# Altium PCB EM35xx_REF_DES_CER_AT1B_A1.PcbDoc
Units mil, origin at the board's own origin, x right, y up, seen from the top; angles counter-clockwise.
Board outline 1630 x 1016 mil, 2 copper layers (Top Layer, Bottom Layer), stack 60.8 mil thick; 50 components, 47 nets, 208 pads, 114 vias.
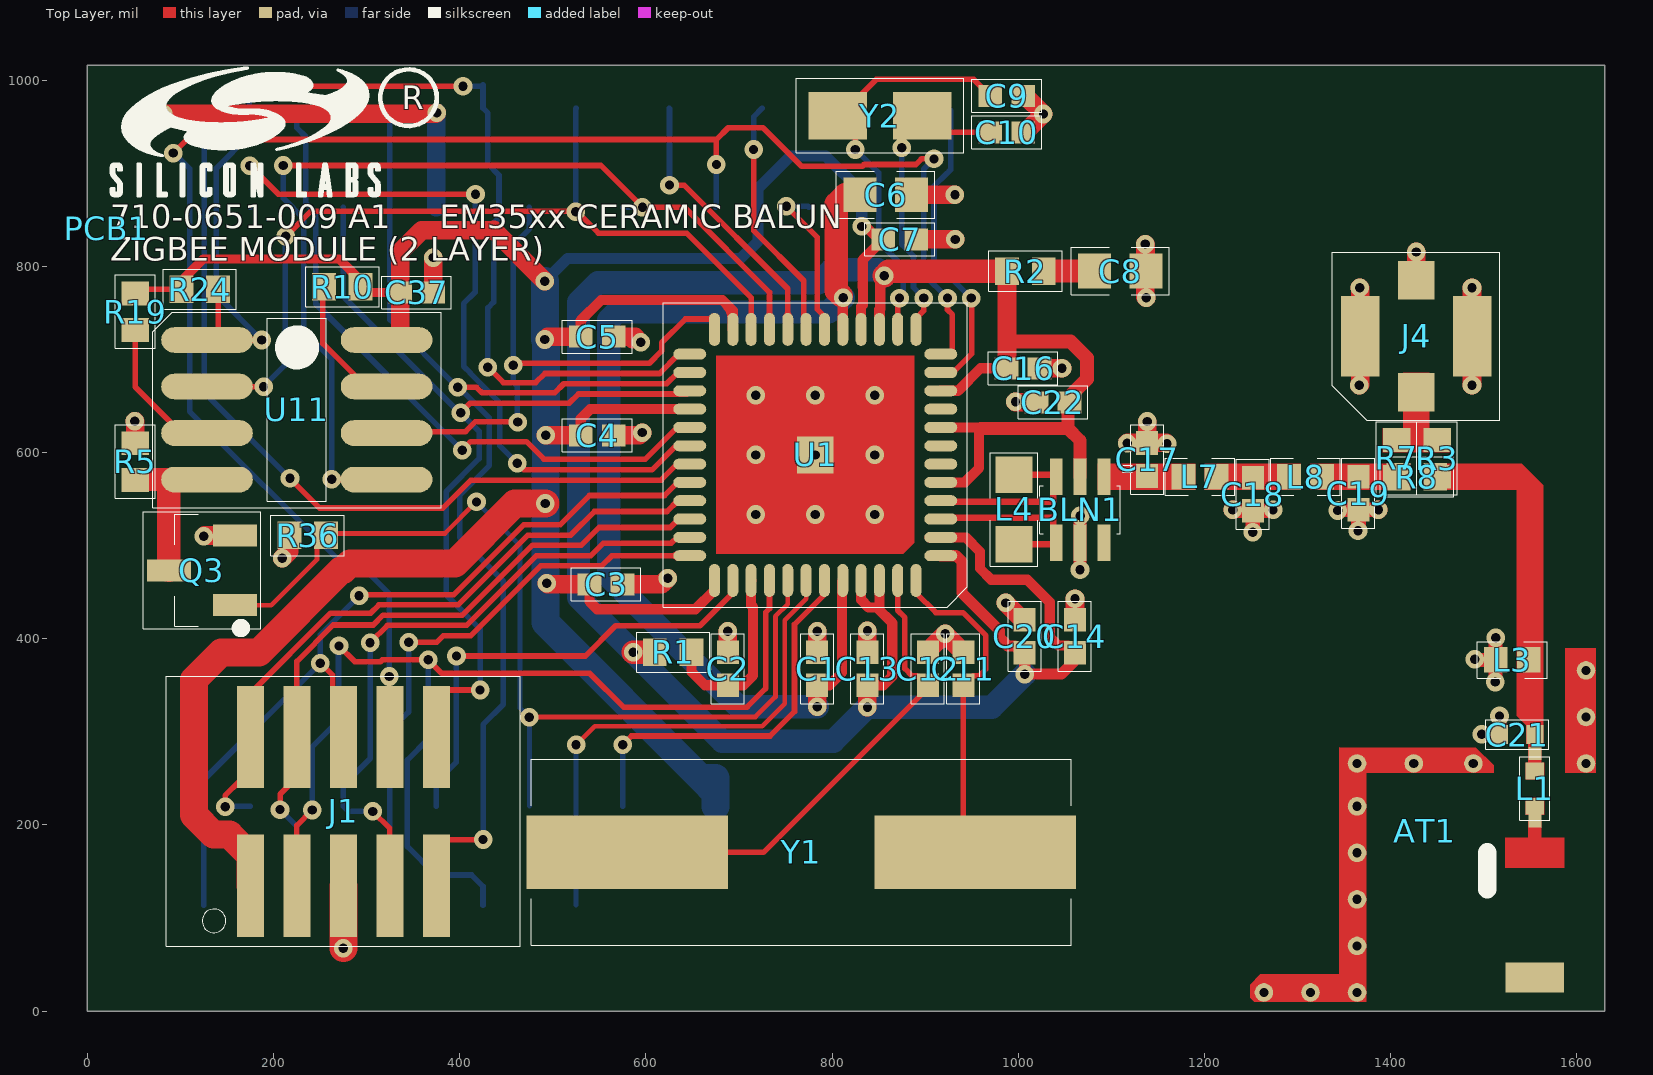
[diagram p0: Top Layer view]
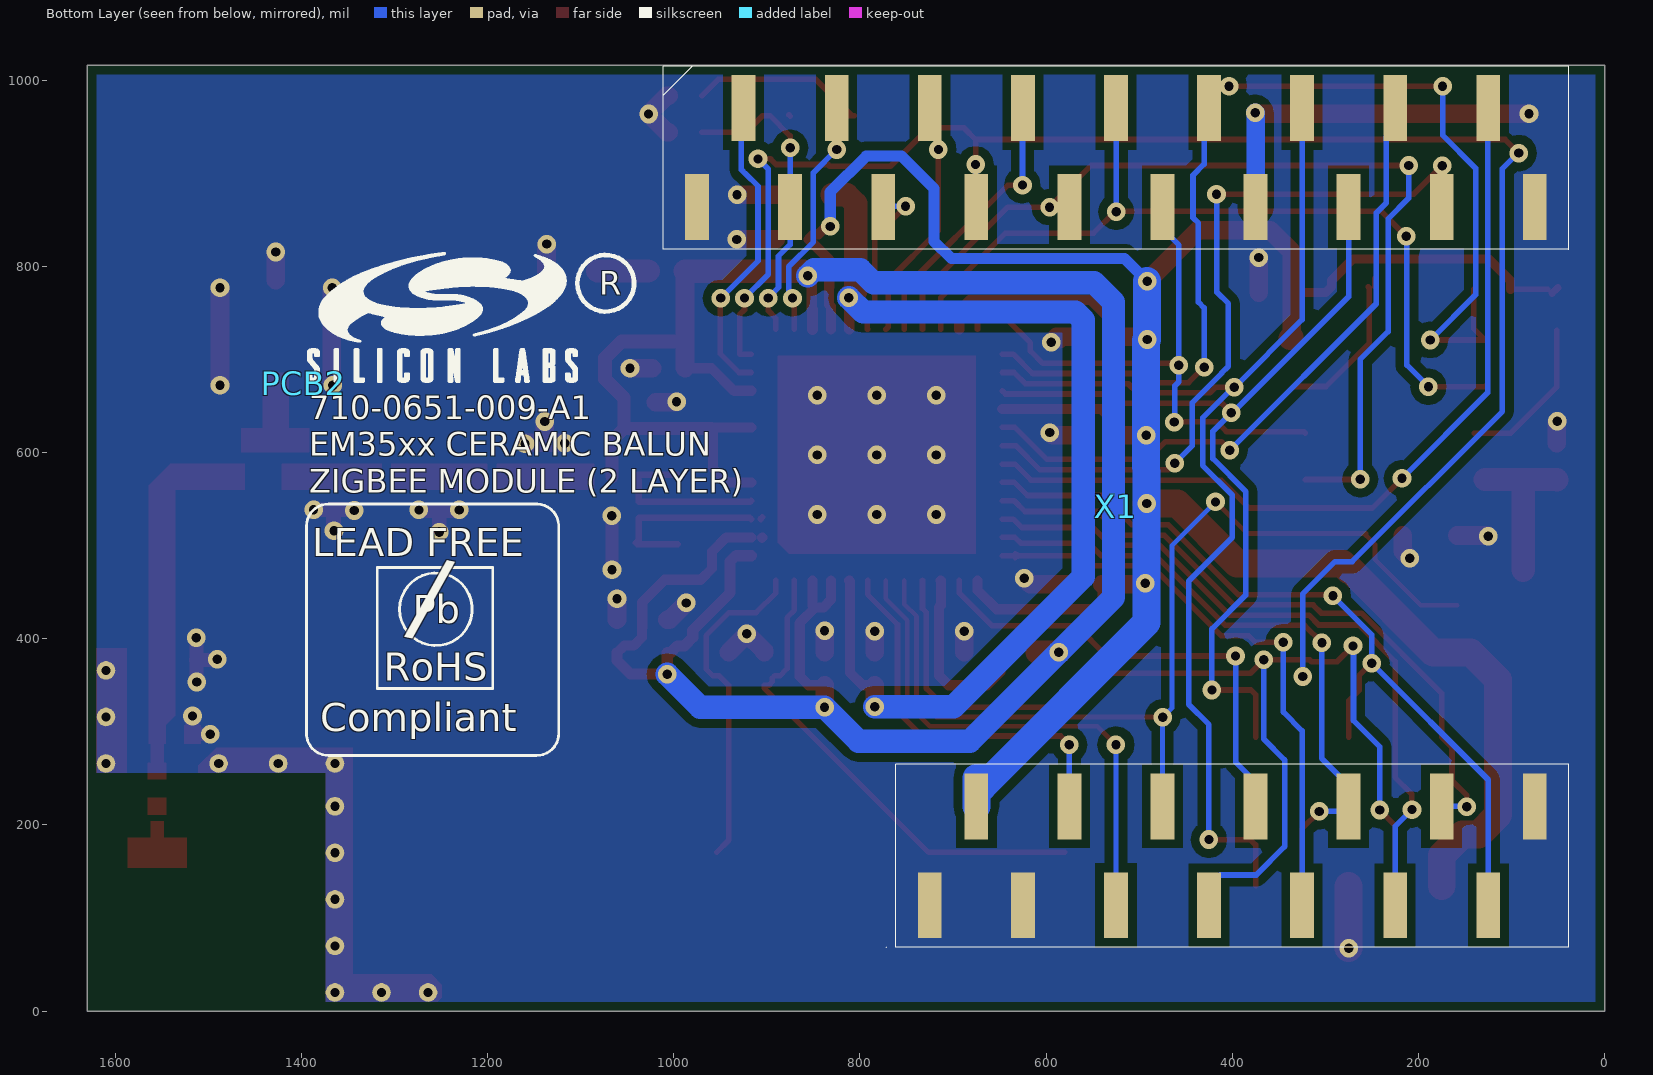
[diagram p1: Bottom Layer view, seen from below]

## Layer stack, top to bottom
Top Solder: solder mask 0.4, Solder Resist, Dk 3.5
Top Layer: signal copper 1.4
Dielectric1: prepreg 58, HR370, Dk 3.9
Bottom Layer: signal copper 1.4
Bottom Solder: solder mask 0.4, Solder Resist, Dk 3.5

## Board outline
0,0 1630,0 1630,1016 0,1016

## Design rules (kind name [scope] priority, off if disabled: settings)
AssemblyTestpoint [All] p1: testpointundercomponent=TRUE minsize=30 maxsize=40 preferedsize=40 minholesize=0 maxholesize=10 preferedholesize=10 testpointgrid=1 usegrid=TRUE gridtolerance=0.01 allowsidetop=TRUE allowsidebottom=TRUE
Clearance "Schematic Clearance Constraint_2" [InNetClass('R8_Nets')] p1: gap=6
Clearance "Schematic Clearance Constraint_1" [InNetClass('R3_Nets')] p2: gap=6
Clearance "Schematic Clearance Constraint" [InNetClass('R7_Nets')] p3: gap=6
Clearance "Schematic Clearance Constraint_6" [InNet('GND')] p4: gap=9.5
Clearance "Schematic Clearance Constraint_5" [InNetClass('L1_Nets')] p5: gap=6
Clearance "Schematic Clearance Constraint_4" [InNetClass('L7_Nets')] p6: gap=6
Clearance "Schematic Clearance Constraint_3" [InNetClass('L8_Nets')] p7: gap=6
Clearance PCB_Only [(InComponentClass('PCB Only'))] p8: gap=0
Clearance [All] p9: gap=5
ComponentClearance ComponentClearance_L1_AT1 [InComponent('AT1') vs InComponent('L1')] p1: gap=0 collisioncheckmode=3 verticalgap=0 showdistances=TRUE
ComponentClearance ComponentClearance_L1_L5 [InComponent('L5') vs InComponent('L1')] p2: gap=0 collisioncheckmode=3 verticalgap=0 showdistances=TRUE
ComponentClearance ComponentClearance_L5_AT1 [InComponent('AT1') vs InComponent('L5')] p3: gap=0 collisioncheckmode=3 verticalgap=0 showdistances=TRUE
ComponentClearance ComponentClearance_1 [All] p4: gap=10 collisioncheckmode=3 verticalgap=10 showdistances=FALSE
DiffPairsRouting [All] p1: maxlimit=10 minlimit=10 mostfreqgap=10 toplayer_minwidth=15 toplayer_maxwidth=15 toplayer_prefwidth=15 bottomlayer_minwidth=15 bottomlayer_maxwidth=15 bottomlayer_prefwidth=15 maxuncoupledlength=500
FabricationTestpoint [All] p1: side=3 testpointundercomponent=TRUE minsize=30 maxsize=40 preferedsize=40 minholesize=0 maxholesize=10 preferedholesize=10 testpointgrid=1 allowsidetop=TRUE allowsidebottom=TRUE usegrid=TRUE gridtolerance=0.01
HoleSize [All] p1: absolutevalues=TRUE maxlimit=100 minlimit=10 maxpercent=80.000 minpercent=20.000
MatchedLengths "Schematic Matched Net Lengths" [InNetClass('L4_Nets')] p1: tolerance=2.5 checknetsindiffpair=TRUE checkdiffpairvsdiffpair=FALSE checkothers=FALSE
MinimumSolderMaskSliver [All] p1: minsoldermaskwidth=2
PlaneClearance [All] p1: clearance=10
PlaneConnect [All] p1: planeconnectstyle=Direct reliefexpansion=20 reliefentries=4 reliefconductorwidth=10 reliefairgap=10
PolygonConnect PolygonConnect_3 [All vs IsNamedPolygon('GROUND')] p1: connectstyle=Direct reliefconductorwidth=10 reliefentries=4 polygonreliefangle="90 Angle" airgapwidth=10
PolygonConnect PolygonConnect_2 [All vs IsNamedPolygon('GROUND')] p2: connectstyle=Direct reliefconductorwidth=10 reliefentries=4 polygonreliefangle="90 Angle" airgapwidth=10
PolygonConnect PolygonConnect_1 [All vs IsNamedPolygon('GROUND')] p3: connectstyle=Relief reliefconductorwidth=10 reliefentries=4 polygonreliefangle="90 Angle" airgapwidth=10
PolygonConnect [All] p4: connectstyle=Direct reliefconductorwidth=10 reliefentries=4 polygonreliefangle="90 Angle" airgapwidth=10
RoutingVias [All] p1: holewidth=10 width=20 viastyle="Through Hole" minholewidth=10 minwidth=20 maxholewidth=10 maxwidth=40
ShortCircuit "Schematic Short-Circuit Constraint" [InNet('GND')] p1: allowed=TRUE
ShortCircuit ShortCircuit_AT1_GND [InNet('NetAT1_1') vs InNet('GND')] p2: allowed=TRUE
ShortCircuit ShortCircuit_AT1_L1 [InPolygon vs InNet('NetL1_1')] p3: allowed=TRUE
ShortCircuit [All] p4: allowed=FALSE
SilkToSilkClearance SilkToSilkClearance_1 [(InComponentClass('PCB Only')) vs (InComponentClass('PCB Only'))] p1: silktosilkclearance=0
SilkToSilkClearance SilkToSilkClearance_2 [InComponent('U11')] p2: silktosilkclearance=0
SilkToSilkClearance SilkToSilkClearance_L1 [InComponent('L1')] p3: silktosilkclearance=0
SilkToSilkClearance SilkToSilkClearance_L5 [InComponent('L5')] p4: silktosilkclearance=0
SilkToSilkClearance [All] p5: silktosilkclearance=0.1
SilkToSolderMaskClearance SilkscreenOverComponent_L1 [InComponent('AT1') vs InComponent('L1')] p1: minsilkscreentomaskgap=0 clearancetoexposedcopper=TRUE
SilkToSolderMaskClearance SilkscreenOverComponent_AT1 [InComponent('AT1')] p2: minsilkscreentomaskgap=0 clearancetoexposedcopper=TRUE
SilkToSolderMaskClearance SilkscreenOverComponent_L5_1 [InComponent('AT1') vs InComponent('L5')] p3: minsilkscreentomaskgap=0 clearancetoexposedcopper=TRUE
SilkToSolderMaskClearance SilkscreenOverComponentPads [IsPad] p4: minsilkscreentomaskgap=0.1 clearancetoexposedcopper=TRUE
SolderMaskExpansion [All] p1: expansion=1
Width "Schematic Width Constraint_3" [InNetClass('R3_Nets')] p1: maxlimit=60 minlimit=6 preferedwidth=28
Width "Schematic Width Constraint_2" [InNetClass('R8_Nets')] p2: maxlimit=60 minlimit=6 preferedwidth=28
Width "Schematic Width Constraint_1" [InNetClass('R7_Nets')] p3: maxlimit=60 minlimit=6 preferedwidth=28
Width "Schematic Width Constraint_14" [InNetClass('C22_Nets')] p4: maxlimit=40 minlimit=5 preferedwidth=20
Width "Schematic Width Constraint_13" [InNetClass('C6_Nets')] p5: maxlimit=40 minlimit=5 preferedwidth=20
Width "Schematic Width Constraint_12" [InNetClass('C37_Nets')] p6: maxlimit=40 minlimit=5 preferedwidth=20
Width "Schematic Width Constraint_11" [InNetClass('L1_Nets')] p7: maxlimit=60 minlimit=6 preferedwidth=28
Width "Schematic Width Constraint_10" [InNetClass('L7_Nets')] p8: maxlimit=60 minlimit=6 preferedwidth=28
Width "Schematic Width Constraint_9" [InNetClass('L8_Nets')] p9: maxlimit=60 minlimit=6 preferedwidth=28
Width "Schematic Width Constraint" [InNetClass('L4_Nets')] p10: maxlimit=10 minlimit=5 preferedwidth=7
Width [All] p11: maxlimit=40 minlimit=4 preferedwidth=5
18 further rules are at their usual default settings.

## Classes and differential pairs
component class "PCB Only": AT1 PCB1 PCB2
net class AT1_Nets: GND NetAT1_1 NetAT1_4
net class BLN1_Nets: 1V8 GND NetBLN1_1 NetBLN1_6 RF_N RF_P
net class C1_Nets: 1V2_CORE GND
net class C2_Nets: GND NetC2_1
net class C3_Nets: GND VBRD
net class C4_Nets: GND VBRD
net class C5_Nets: GND VBRD
net class C6_Nets: 1V2_CORE GND
net class C7_Nets: GND VBRD
net class C8_Nets: GND NetC8_1
net class C9_Nets: GND PC7
net class C10_Nets: GND PC6
net class C11_Nets: GND OSCA
net class C12_Nets: GND OSCB
net class C13_Nets: 1V8 GND
net class C14_Nets: 1V8 GND
net class C16_Nets: 1V8 GND
net class C17_Nets: GND NetBLN1_1
net class C18_Nets: GND NetC18_1
net class C19_Nets: GND NetC19_1
net class C20_Nets: 1V8 GND
net class C22_Nets: 1V8 GND
net class C37_Nets: GND VBRD
net class J1_Nets: GND JCLK NRESET PA4 PA5 PC0 PC2 PC3 PC4 VBRD
net class J4_Nets: GND NetJ4_1
net class L1_Nets: NetAT1_1 NetAT1_4
net class L3_Nets: GND NetAT1_4
net class L4_Nets: RF_N RF_P
net class C21_Nets: GND NetAT1_4
net class L7_Nets: NetBLN1_1 NetC18_1
net class L8_Nets: NetC18_1 NetC19_1
net class Q3_Nets: GND NSF_GND PB7
net class R1_Nets: 1V8 NetC2_1
net class R2_Nets: 1V8 NetC8_1
net class R3_Nets: NetAT1_4 NetJ4_1
net class R5_Nets: GND NSF_GND
net class R7_Nets: NetC19_1 NetJ4_1
net class R8_Nets: NetAT1_4 NetC19_1
net class R10_Nets: NSF_HOLD VBRD
net class R19_Nets: NSF_WP VBRD
net class R24_Nets: PA3 VBRD
net class R36_Nets: GND PB7
net class U1_Nets: 1V2_CORE 1V8 GND JCLK NetC2_1 NetU1_9 NRESET OSCA OSCB PA0 PA1 PA2 PA3 PA4 PA5 PA6 PA7 PB0 PB1 PB2 PB3 PB4 PB5 PB6 PB7 PC0 PC1 PC2 PC3 PC4 PC5 PC6 PC7 RF_N RF_P TX_ALT_N TX_ALT_P VBRD
net class U11_Nets: NSF_GND NSF_HOLD NSF_WP PA0 PA1 PA2 PA3 VBRD
net class X1_Nets: GND JCLK NRESET PA0 PA1 PA2 PA3 PA4 PA5 PA6 PA7 PB0 PB1 PB2 PB3 PB4 PB5 PB6 PB7 PC0 PC1 PC2 PC3 PC4 PC5 PC6 PC7 VBRD
net class Y1_Nets: OSCA OSCB
net class Y2_Nets: PC6 PC7
differential pair RF: +RF_P -RF_N

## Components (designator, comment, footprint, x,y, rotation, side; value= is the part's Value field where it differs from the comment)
AT1 "Value" Ant-Johanson-2450AT18B100 1630,0 r0 top
BLN1 "CHIP MULTILAYER CERAMIC, 2.4 GHZ. 50/100 Ohm" BLN_0805 1092,574 r0 top
C1 "10NF" C_0402 784,350 r0 top
C2 "0.47uF" C_0402 688,350 r0 top
C3 "0.1uF" C_0402 539.56,458.5 r270 top
C4 "0.1uF" C_0402 530,618.5 r270 top
C5 "0.1uF" C_0402 530,724.5 r270 top
C6 "1.0uF" C_0603 830,877 r0 top
C7 "0.1uF" C_0402 855,829 r270 top
C8 "2.2uF" C_0603 1082,795 r0 top
C9 "33pF, (DNI)" C_0402 970,983.2 r270 top
C10 "22PF, (DNI)" C_0402 970,944.1 r270 top
C11 "22PF" C_0402 941,350 r0 top
C12 "22PF" C_0402 903,350 r0 top
C13 "10pF" C_0402 838,350 r0 top
C14 "10NF" C_0402 1061,385 r0 top
C16 "10NF" C_0402 987.56,690.5 r270 top
C17 "1pF" C_0402 1138.5,575 r0 top
C18 "1.8pF" C_0402 1252,573 r180 top
C19 "1pF" C_0402 1365.5,574 r180 top
C20 "10NF" C_0402 1007,385 r0 top
C21 "0.75pF" C_0402_Johanson_AT1B 1555.1,297.1 r90 top
C22 "10pF" C_0402 1055,654 r90 top
C37 "10NF, (DNI)" C_0402 336.06,772 r270 top
J1 "FTSH-105-01-F-DV-K, (DNI)" 610-0019-000-REF-DES 175,134.5 r270 top
J4 "U.FL, (DNI)" UFL-R-SMT_1 1427.5,725 r180 top
L1 "5n6H" C_0402_Johanson_AT1B 1555,258 r180 top
L3 "DNI" L_0402 1548.5,377.3 r180 top
L4 "2.7nH" L_0603 995.5,576.3 r0 top
L7 "2n7H" L_0402 1177.56,574 r0 top
L8 "2n7H" L_0402 1291,574 r0 top
LOGO1 "SiliconLabsLogo_100" SiliconLabsLogo_100_Mech-16 3297,-1825.5 r0 top
PCB1 "EM35x Ceramic Balun 2 Layer Reference Design Corporate Logo" 710-0651-009 20.7,840.9 r0 top
PCB2 "Bottom Silk Screen ID and RoHS Text" 710-0651-009_ROHS 1397.6,674.7 r180 bottom
Q3 "2N7002, (DNI)" SOT23-3L 123,473.5 r180 top
R1 "10 Ohm" R_0402 609.63,385.5 r0 top
R2 "1 Ohm" R_0402 988,795 r0 top
R3 "0_OHM, (DNI)" R_0402 1450,574 r90 top
R5 "0_OHM, (DNI)" R_0402 51.4,570.7 r90 top
R7 "0_OHM, (DNI)" R_0402 1406.5,574 r90 top
R8 "0_OHM" R_0402 1408.63,574 r0 top
R10 "100K, (DNI)" R_0402 254.06,778.11 r0 top
R19 "100K, (DNI)" R_0402 51.4,731.63 r90 top
R24 "100K, (DNI)" R_0402 140.5,775.5 r180 top
R36 "100K, (DNI)" R_0402 256.37,511 r180 top
U1 "EM35xx" EM357 782,597.5 r0 top
U11 "2M, (DNI)" SOIC127P600-8M 225,646 r0 top
X1 "Dual Row Socket, (DNI)" EM35X_RCM_MODULE_SIDE_SMT 975,916.85 r180 bottom locked
Y1 "24.000MHZ, 18PF LOAD" HC-49-SMD 767,170.5 r180 top
Y2 "32.768KHz, 12.5pF, (DNI)" IL3X 851.5,962 r180 top

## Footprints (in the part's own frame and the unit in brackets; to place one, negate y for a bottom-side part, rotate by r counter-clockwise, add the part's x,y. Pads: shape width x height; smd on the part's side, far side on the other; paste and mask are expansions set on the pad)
610-0019-000-REF-DES [mil] "old footprint with keepout for cable connector"
  rect 110x29 smd: 1(0,0) 2(-160,0) 3(0,50) 4(-160,50) 5(0,100) 6(-160,100) 7(0,150) 8(-160,150) 9(0,200) 10(-160,200)
  silkscreen extent -225,-90 65,290, body extent -148,-25 -12,225, height 225
710-0651-009 [mil] "EM35x Ceramic Balun"
  silkscreen extent 5,35 355,173
710-0651-009_ROHS [mil] "EM35x CERAMIC BALUN"
  silkscreen extent 3,-400 355,139
Ant-Johanson-2450AT18B100 [mil]
  rect 14x14 smd paste-100 mask-100: 1(-75,204) 3(-113.17,296.9) 4(-74.99,276.7)
  rect 63x32 smd paste+0 mask+0: 2(-75,36)
  round 20 hole 10 mask+0: 5(-20,366) 6(-20,316) 7(-20,266) 8(-141,266) 9(-205,266) 10(-266,266) 11(-266,220) 12(-266,170) 13(-266,120) 14(-266,70) 15(-266,20) 17(-316,20) 18(-366,20)
  Top Layer region: -68,186 -68,204 -82,204 -82,186
  Top Layer region: -43.5,154 -43.5,186 -106.5,186 -106.5,154
  Top Layer region: -65,267 -85,267 -85,249 -65,249
  Top Layer region: -65,229 -85,229 -85,211 -65,211
  Top Layer region: -122,307 -122,287 -104,287 -104,307
  Top Layer region: -84,307 -84,287 -66,287 -66,307
  Top Layer region: -68,267 -68,287 -82,287 -82,267
  Multi-Layer pour cut-out: -256,0 -256,256 0,256 0,0
  silkscreen extent -126,131 -126,170, body extent -114,40 -43,307, height 40
BLN_0805 [mm]
  rect 0.35x1 smd: 1(0,0) 2(-0.65,0) 3(-1.3,0) 4(-1.3,-1.8) 5(-0.65,-1.8) 6(0,-1.8)
  silkscreen extent -1.75,-1.55 0.78,0.31
C_0402 [mm]
  rect 0.6x0.65 smd mask+0.051: 1(0,0) 2(0,0.9)
  silkscreen extent -0.45,-0.5 0.45,1.4, body extent -0.28,-0.05 0.28,0.97, height 1.02
C_0402_Johanson_AT1B [mil] "Special footprint for Antenna"
  rect 20x18 smd paste+0 mask+0: 1(0,0) 2(0,38)
  silkscreen extent -16,-15 16,53
C_0603 [mm]
  rect 0.9x0.95 smd mask+0.051: 1(0,0) 2(1.4,0)
  silkscreen extent -0.64,-0.65 2.04,0.65, body extent -0.09,-0.39 1.51,0.39, height 0.89
EM35X_RCM_MODULE_SIDE_SMT [mm]
  rect 0.65x1.8 smd: 1(0,-1.35) 2(1.27,1.35) 3(2.54,-1.35) 4(3.81,1.35) 5(5.08,-1.35) 6(6.35,1.35) 7(7.62,-1.35) 8(8.89,1.35) 9(10.16,-1.35) 10(11.43,1.35) 11(12.7,-1.35) 12(13.97,1.35) 13(15.24,-1.35) 14(16.51,1.35) 15(17.78,-1.35) 16(19.05,1.35) 17(20.32,-1.35) 18(21.59,1.35) 19(22.86,-1.35) 20(22.86,-17.7) 21(21.59,-20.4) 22(20.32,-17.7) 23(19.05,-20.4) 24(17.78,-17.7) 25(16.51,-20.4) 26(15.24,-17.7) 27(13.97,-20.4) 28(12.7,-17.7) 29(11.43,-20.4) 30(10.16,-17.7) 31(8.89,-20.4) 32(7.62,-17.7) 33(6.35,-20.4)
  silkscreen extent -0.93,-21.56 23.78,2.5
EM357 [mm]
  oval 0.9x0.3 smd paste+0 mask+0: 1(3.425,-2.75) 2(3.425,-2.25) 3(3.425,-1.75) 4(3.425,-1.25) 5(3.425,-0.75) 6(3.425,-0.25) 7(3.425,0.25) 8(3.425,0.75) 9(3.425,1.25) 10(3.425,1.75) 11(3.425,2.25) 12(3.425,2.75) 25(-3.425,2.75) 26(-3.425,2.25) 27(-3.425,1.75) 28(-3.425,1.25) 29(-3.425,0.75) 30(-3.425,0.25) 31(-3.425,-0.25) 32(-3.425,-0.75) 33(-3.425,-1.25) 34(-3.425,-1.75) 35(-3.425,-2.25) 36(-3.425,-2.75)
  oval 0.3x0.9 smd paste+0 mask+0: 13(2.75,3.425) 14(2.25,3.425) 15(1.75,3.425) 16(1.25,3.425) 17(0.75,3.425) 18(0.25,3.425) 19(-0.25,3.425) 20(-0.75,3.425) 21(-1.25,3.425) 22(-1.75,3.425) 23(-2.25,3.425) 24(-2.75,3.425) 37(-2.75,-3.425) 38(-2.25,-3.425) 39(-1.75,-3.425) 40(-1.25,-3.425) 41(-0.75,-3.425) 42(-0.25,-3.425) 43(0.25,-3.425) 44(0.75,-3.425) 45(1.25,-3.425) 46(1.75,-3.425) 47(2.25,-3.425) 48(2.75,-3.425)
  rect 1x1 smd paste-1 mask+0: 49(0,0)
  Top Layer pour cut-out: -3.039,-3.503 -3.499,-3.503 -3.499,-3.043 -3.039,-3.043 -3.039,-3.503
  Top Layer pour cut-out: -3.039,3.04 -3.499,3.04 -3.499,3.5 -3.039,3.5 -3.039,3.04
  Top Layer pour cut-out: 3.507,3.04 3.047,3.04 3.047,3.5 3.507,3.5 3.507,3.04
  Top Layer pour cut-out: 3.506,-3.505 3.046,-3.505 3.046,-3.045 3.506,-3.045 3.506,-3.505
  Top Layer region: 2.7,-2.4 2.4,-2.7 -2.7,-2.7 -2.7,2.7 2.7,2.7
  silkscreen extent -4.15,-4.15 4.15,4.15, body extent -3.51,-3.51 3.51,3.51, height 0.9
HC-49-SMD [mm]
  rect 5.5x2 smd: 1(-4.75,0) 2(4.75,0)
  silkscreen extent -7.37,-2.54 7.37,2.54, body extent -7.24,-2.41 7.24,2.41, height 4.06
IL3X [mil]
  rect 62.99x51.18 smd: 1(-45.28,0) 2(45.28,0)
  silkscreen extent -90,-40 90,40, body extent -63,-30 63,30, height 36
L_0402 [mm]
  rect 0.65x0.7 smd: 1(0,0) 2(0.9,0)
  silkscreen extent -0.5,-0.5 1.4,0.5, body extent -0.06,-0.28 0.95,0.28, height 1.02
L_0603 [mm]
  rect 1x1 smd: 1(0,0) 2(0,-1.9)
  silkscreen extent -0.65,-2.5 0.65,0.6, body extent -0.39,-1.74 0.39,-0.14, height 0.89
R_0402 [mm]
  rect 0.65x0.75 smd: 1(0,0) 2(1,0)
  silkscreen extent -0.5,-0.55 1.5,0.55, body extent -0.01,-0.28 1,0.28, height 1.02
SiliconLabsLogo_100_Mech-16 [mil] "Silicon Labs Logo for Sheet Layer"
SOIC127P600-8M [mm] "SOIC, 8-Leads, Body 4.9x3.9mm, Pitch 1.27mm, IPC Low Density"
  oval 2.5x0.7 smd: 1(-2.45,1.905) 2(-2.45,0.635) 3(-2.45,-0.635) 4(-2.45,-1.905) 5(2.45,-1.905) 6(2.45,-0.635) 7(2.45,0.635) 8(2.45,1.905)
  silkscreen extent -3.94,-2.67 3.94,2.67, body extent -2,-2.5 2,2.5, height 1.75
SOT23-3L [mm] "SOT23, 3-Leads, Body 2.9x1.3mm, Pitch 0.95mm, Lead Span 2.5mm, IPC High Density"
  rect 1.2x0.6 smd: 1(-0.9,0.95) 2(-0.9,-0.95) 3(0.9,0)
  silkscreen extent -1.6,-1.6 1.6,1.7, body extent -0.7,-1.5 0.7,1.5, height 1.1
UFL-R-SMT_1 [mm]
  rect 1x1.05 smd: 1(0,1.525) 4(0,-1.525)
  rect 1.05x2.2 smd: 2(-1.525,0) 3(1.525,0)
  silkscreen extent -2.29,-2.29 2.29,2.29

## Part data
AT1: library part 600-0044-000
BLN1: library part 566-0075-000, "Balun 0805"
C1 C14 C16 C20: library part 550-0036-000
C2: library part 550-0037-000
C3 C4 C5 C7: library part 550-0034-000
C6: library part 550-0033-000
C8: library part 550-0038-000
C9: library part 550-0039-000-DNI
C10: library part 550-2201-050-DNI
C11 C12: library part 550-2201-050
C13 C21 C22: library part 550-1001-050
C17 C19: library part 550-0040-000
C18: library part 550-1P8A-050
C37: library part 550-1032-025-DNI
J1: library part 610-0045-000-DNI, "CONNECTOR, HEADER, SHROUDED, 10 POSITION, DUAL ROW, VERTICAL, 0.050\""
J4: library part 610-0081-000-DNI, "U.FL RF Coaxial Connector"
L1: library part 566-0077-000, "Design Placeholder"
L3: library part 566-0000-TBD, "Design Placeholder"
L4: library part 566-0076-000, "Design Placeholder"
L7 L8: library part 566-2N7A-000, "Design Placeholder"
LOGO1: "Company Logo in PCB Title Block"
PCB1: library part 710-0651-009, "PCB BoM ID and Top Side Silk Screen Identifier"
PCB2: library part 710-0651-009_ROHS, "Bottom Side Silk Screen Identifier"
Q3: library part 545-0047-000-DNI, "MOSFET N-Channel"
R1: library part 555-1001-010
R2: library part 555-1R05-016
R3 R5 R7: library part 555-0000-000-DNI
R8: library part 555-0000-000
R10 R19 R24 R36: library part 555-1045-016-DNI
U1: library part 540-035XX-000, "IC, EM357, ZIGBEE/802.15.4 RF SOLUTION, ARM CORTEX-M3, 12K RAM, 192K FLASH, QFN-48"
U11: library part 510-1040-000-DNI, "IC - MEMORY, SERIAL FLASH, 2M (2M X 1, 1M X 2), 2.7 V - 3.6 V, -40C  85C, 8-SOIC (0.154\", 3.90MM WIDTH)"
X1: library part 610-0010-DNI, "610-0010-DNI"
Y1: library part 565-2400-009, "OSCILLATOR, CRYSTAL, 24.000MHZ, 18PF LOAD, +/-10PPM TOLERANCE, +/-25PPM STABILITY, -40C TO 85C, AT49"
Y2: library part 565-3271-001-DNI

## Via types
v1: diameter 20, hole 10, Top Layer to Bottom Layer, 114 vias

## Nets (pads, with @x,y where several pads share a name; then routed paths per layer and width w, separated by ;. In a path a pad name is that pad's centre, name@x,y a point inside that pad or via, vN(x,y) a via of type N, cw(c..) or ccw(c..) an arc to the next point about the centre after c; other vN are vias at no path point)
1V2_CORE: C1.1 C6.1 U1.17 U1.44 | length 1141.5
  Top Layer w11: C1.1 797,350 810.81,363.81 810.81,461.94 U1.44 ; U1.17 811.53,766.03 v1(812,766.5) v1@812,768.37
  Top Layer w20: v1(784,327) C1.1
  Top Layer w25: v1@810.13,768.37 804.5,774 804.5,867.5 814,877 C6.1
  Bottom Layer w25: v1(784,327) 699.5,327 560,466.5 560,742.5 568.5,751 796.5,751 v1(812,766.5)
1V8: BLN1.2 C13.1 C14.1 C16.1 C20.1 C22.1 R1.1 R2.1 U1.1 U1.2 U1.5 U1.8 U1.10 U1.15 U1.45 U1.46 | length 2785
  Top Layer w11: U1.45 831.21,441.79 839.5,433.5 848.36,433.5 ; C13.1 855,350 864.81,359.81 864.81,417.05 848.36,433.5 ; U1.46 850.9,436.04 848.36,433.5 ; U1.2@904.84,508.92 U1.2@905.26,508.5 ; U1.2 943.58,508.92 959,493.5 959,475.5 971,463.5 1009.76,463.5 1034,439.26 1034,412 1034.19,411.81 1034.19,401.43 1042.98,392.64 1053.36,392.64 C14.1 ; U1.5 942.47,567.97 958,583.5 958,627.03 U1.8 ; U1.10 935.4,666.4 959.5,690.5 C16.1
  Top Layer w11.5: U1.15 850.9,753.63 851.75,754.48 851.75,785.75 v1(856,790)
  Top Layer w12: U1.1 933.27,489.23 939.5,483 939.5,449.02 979.69,408.83 979.69,401.22 988.77,392.14 996.38,392.14 1003.52,385 C20.1 v1(1007,362) 1046.5,362 1061,376.5 C14.1
  Top Layer w14: 959.34,625.69 1053.66,625.69 ; C22.1@1055,660.32 1053.66,658.98 1053.66,625.69 ; BLN1.2 1066.41,612.94 1053.66,625.69
  Top Layer w15: 988,721.5 990.19,719.31 1056.37,719.31 1074,701.68 1074,679.32 C22.1@1055,660.32
  Top Layer w20: v1(838,326.5) C13.1 ; C16.1 988,690.94 988,721.5 R2.1
  Top Layer w25: v1(586.5,385.5) R1.1 ; v1(856,790) 860.69,794.69 987.69,794.69 R2.1
  Bottom Layer w25: v1(856,790) 849.5,796.5 799.57,796.5 785.57,782.5 548.5,782.5 527.5,761.5 527.5,444.5 v1(586.5,385.5) 682,290 801.5,290 v1(838,326.5) 971.5,326.5 v1(1007,362)
GND: AT1.3 AT1.5 AT1.6 AT1.7 AT1.8 AT1.9 AT1.10 AT1.11 AT1.12 AT1.13 AT1.14 AT1.15 AT1.17 AT1.18 BLN1.5 C1.2 C2.2 C3.2 C4.2 C5.2 C6.2 C7.2 C8.2 C9.2 C10.2 C11.2 C12.2 C13.2 C14.2 C16.2 C17.2 C18.2 C19.2 C20.2 C21.2 C22.2 C37.2 J1.5 J4.2 J4.3 J4.4 L3.2 Q3.2 R5.2 R36.2 U1.49 X1.1 X1.13 X1.19 X1.20 X1.31 X1.33 | length 1761.9
  Top Layer w14: v1@1067,532 v1(1066.5,532) 1066.41,531.91 BLN1.5 v1(1066.41,474.09) v1@1067.5,473
  Top Layer w15: v1(1490.4,377.9) 1491,377.3 L3.2 ; v1(1498.1,297.4) 1516.33,297.4 AT1.3 1517.1,297.16 v1(1517.1,317) ; v1(1512.6,353.6) 1512.6,376.84 L3.2 ; v1(1513,401) 1513,377.36 L3.2
  Top Layer w16: v1(1230.4,538.4) 1231.24,537.56 C18.2 ; v1(1252.1,514.3) 1252,514.4 C18.2 ; v1(1273.8,538.4) 1272.96,537.56 C18.2 ; v1@1344.16,538.56 C19.2 ; v1@1364.3,516.7 v1(1365.1,515.9) 1365.5,516.3 C19.2 ; v1(1387,538.6) C19.2
  Top Layer w20: v1(51,633.8) 51.4,633.4 R5.2 ; v1(81.3,964) 81.5,964.2 374.5,964.2 v1(375.5,965.2) ; v1@125.9,510.9 Q3.2 ; v1(209.5,486.4) 217,493.9 R36.2 ; C37.2 v1(371.5,809.5) ; C4.2 593,618.5 v1(596,621.5) ; C5.2 588.5,724.5 v1@585.9,721.9 ; C3.2@575.5,457 575,457.5 C3.2 617,458.5 v1(623.5,465) ; C2.2 v1(688,408) ; C1.2 v1(784,408) ; C13.2 v1(838,408.5) ; C6.2 v1(932,877) ; C7.2 v1(932.5,829) ; C12.2 903,387 v1(921.5,405.5) 921.5,404.94 C11.2 ; v1(986.5,438.5) 1004.56,420.44 C20.2 ; v1(997,654.5) 997.5,654 C22.2 ; C10.2 1007.4,944.1 v1(1027.1,963.8) 1007.7,983.2 C9.2 ; C16.2 v1(1047,690.5) ; C14.2 v1(1061,443) ; v1@1117.44,610.44 C17.2 ; C8.2 1137.12,823.38 v1(1136.5,824) 1136.5,767.5 v1(1137.5,766.5) ; v1@1138.5,633.1 C17.2 ; v1@1159.06,610.44 C17.2 ; v1(1230.4,538.4) v1@1230.56,538.56 ; v1(1366.5,672.5) 1367.46,673.46 J4.3 1367.46,776.54 v1(1367,777) ; v1(1387,538.6) v1(1387,538.6) ; J4.4 v1(1427.5,815.5) ; v1(1487.5,672.5) v1(1487.5,672.5) J4.2 v1(1487.5,777) v1(1487.5,777)
  Top Layer w30: v1(275,67.5) J1.5
  Bottom Layer w20: X1.13 375,964.7 v1(375.5,965.2)
  other v1: 125,510 717.98,533.48 782,533.48 846.02,533.48 1343.4,537.8 717.98,597.5 782,597.5 846.02,597.5 1117,610 1159.9,609.6 1138.8,633.4 717.98,661.52 782,661.52 846.02,661.52 594.5,718.5
JCLK: J1.6 U1.32 X1.21 | length 896.8
  Top Layer w6: v1(250.3,373.8) 263.7,360.4 263.7,344.5 275,333.2 J1.6 ; v1(291.9,446.1) 293.2,447.4 393.72,447.4 468.63,522.31 507.81,522.31 539.4,553.9 620,553.9 634.07,567.97 U1.32
  Bottom Layer w6: X1.21 125,248.5 v1(250.3,373.8) 250.3,404.5 v1(291.9,446.1)
NetAT1_1: AT1.1 L1.2
NetAT1_4: AT1.4 C21.1 L1.1 L3.1 R3.1 R8.2
NetBLN1_1: BLN1.1 C17.1 L7.1
NetC2_1: C2.1 R1.2 U1.39 | length 200.5
  Top Layer w11: R1.2 649,364.5 663.5,350 C2.1 704.5,350 715.19,360.69 715.19,433.94 713,436.13 713,462.56 U1.39
NetC8_1: C8.1 R2.2 | length 54.6
  Top Layer w25: R2.2 C8.1
NetC18_1: C18.1 L7.2 L8.1
NetC19_1: C19.1 L8.2 R7.1 R8.1
NetJ4_1: J4.1 R3.2 R7.2
NRESET: J1.8 U1.12 X1.7 | length 1819.5
  Top Layer w6: v1(92.3,921.8) 106.9,936.4 675.9,936.4 688.5,949 725.8,949 767.2,907.6 832.46,907.6 834.36,909.5 890.1,909.5 896.1,915.5 v1(909.5,915.5) ; v1(675.8,909.5) 675.8,936.4 ; U1.12 929.23,705.77 929.23,748.27 924,753.5 v1(924,766)
  Bottom Layer w6: v1(92.3,921.8) 93.1,921.8 109.9,905 109.9,644.2 271.3,482.8 289.6,482.8 324.4,448 324.4,371 ; X1.7 675.8,864.5 v1(675.8,909.5) ; v1(909.5,915.5) 898.5,904.5 898.5,791.5 v1(924,766)
  other v1: 324.4,359.5
NSF_GND: Q3.3 R5.1 U11.4 | length 174.8
  Top Layer w25: R5.1 51.7,571 U11.4 ; Q3.3 U11.4@87.57,571
NSF_HOLD: R10.1 U11.7 | length 169.4
  Top Layer w6: R10.1@247.13,778.11 R10.1@247.13,787 ; R10.1 253,777.05 253,717.15 299.15,671 U11.7@332.96,671
NSF_WP: R19.1 U11.3 | length 170.3
  Top Layer w6: R19.1 51.4,670.5 100.9,621 U11.3@140.04,621
OSCA: C11.1 U1.48 Y1.1 | length 359.8
  Top Layer w6: U1.48 890.27,449.23 911.5,428 940.72,428 965.31,403.41 965.31,367.47 957.99,360.14 951.14,360.14 C11.1 941,183.51 Y1.1
OSCB: C12.1 U1.47 Y1.2 | length 531.4
  Top Layer w6: Y1.2 726.2,170.5 903,347.3 C12.1 898,350 894.3,353.7 894.3,357.7 891.86,360.14 886.01,360.14 878.31,367.85 878.31,422.64 870.58,430.36 U1.47
PA0: U1.21 U11.5 X1.9 | length 1113.1
  Top Layer w6: v1(210.5,908.4) 551.6,908.4 v1(596.3,863.7) ; v1(262.6,571.3) 321.16,571.3 U11.5 263.9,571 v1@263.1,570.2 ; v1@599.4,863.7 641.2,863.7 732.79,772.11 U1.21
  Bottom Layer w6: v1(210.5,908.4) 210.5,873.2 232.6,851.1 232.6,730 262.6,700 v1(262.6,571.3) ; X1.9 v1(596.3,863.7)
PA1: U1.22 U11.2 X1.10 | length 927.4
  Top Layer w6: U11.2 128.74,670.8 v1(189.3,670.8) ; v1(213.1,832.3) 240.3,859.5 525.2,859.5 548.9,835.8 643.8,835.8 713.1,766.5 U1.22
  Bottom Layer w6: v1(189.3,670.8) 212.4,693.9 212.4,831.6 v1(213.1,832.3) ; v1(524.7,858.9) 524.7,969.7 X1.10
PA2: U1.24 U11.6 X1.11 | length 660.3
  Top Layer w6: U11.6 323.06,622.6 406.26,622.6 416.86,633.2 461.8,633.2 v1(462.2,632.8) ; v1@457.8,693.7 457.5,694 v1(457.4,694) 459.4,696 603.82,696 617,709.18 617,718 642.5,743.5 672,743.5 673.73,741.77 U1.24 ; 665.14,743.5 ccw(c665.14,752.75) U1.24@671.68,746.21 ; 665.14,743.5 ccw(c665.14,752.75) U1.24@671.68,746.21 ; 665.14,743.5 ccw(c665.14,752.75) U1.24@671.68,746.21
  Bottom Layer w6: v1(462.2,632.8) 461.7,633.3 461.7,671.8 457.4,676.1 v1(457.4,694) 457.4,822.9 474.8,840.3 X1.11@474.8,863.5
PA3: R24.1 U1.25 U11.1 X1.12 | length 1228.9
  Top Layer w6: R24.1 140.5,732.96 U11.1 v1(187.2,721) ; v1(174.1,993.7) v1(403.6,993.7) ; v1(430.2,691.8) 446.9,675.1 481.6,675.1 491.5,685 614.6,685 635.37,705.77 U1.25
  Bottom Layer w6: v1(174.1,993.7) 174.1,941 138.5,905.4 138.5,769.7 v1(187.2,721) ; v1(403.6,993.7) 423.8,993.7 425,994.9 X1.12 430.2,964.8 430.2,910 442.2,898 442.2,852.3 436.5,846.6 436.5,761.7 430.2,755.4 v1(430.2,691.8)
PA4: J1.9 U1.26 X1.14 | length 1229.8
  Top Layer w6: J1.9 375,178.5 380.8,184.3 v1(425.1,184.3) ; v1(397.8,670.1) 418.2,670.1 424.2,664.1 501.9,664.1 511.8,674 622.33,674 634.42,686.08 U1.26
  Bottom Layer w6: X1.14 325,742.9 v1(397.8,670.1) 399.16,670.1 431.9,637.36 431.9,586.36 400,554.46 400,508.8 446.8,462 446.8,329.4 425.1,307.7 v1(425.1,184.3)
PA5: J1.10 U1.27 X1.15 | length 960.1
  Top Layer w6: J1.10 375,340 380,345 v1(421.9,345) ; v1(401,642.8) 411.3,653.1 517.7,653.1 527.6,663 643.76,663 U1.27
  Bottom Layer w6: X1.15 275,767.44 399.64,642.8 v1(401,642.8) 420.9,622.9 420.9,593.6 385.5,558.2 385.5,446.9 421.9,410.5 v1(421.9,345)
PA6: U1.29 X1.16 | length 711.2
  Top Layer w6: v1(402.6,602.6) 411.8,611.8 471.6,611.8 490.4,593 599.5,593 633.53,627.03 U1.29
  Bottom Layer w6: X1.16 225,948.9 234.6,939.3 234.6,868.3 245.3,857.6 245.3,759.9 v1(402.6,602.6)
PA7: U1.18 X1.5 | length 173.5
  Top Layer w6: v1(751,864.5) 784,831.5 784,754.2 792,746.2 792,732.5 U1.18
  Bottom Layer w6: v1(751,864.5) 774.2,864.5 X1.5
PB0: U1.36 X1.25 | length 664.5
  Top Layer w6: v1(345.2,396.4) 375.5,396.4 382.2,403.1 411.64,403.1 486.85,478.31 552.53,478.31 563.45,489.23 U1.36 ; 628.33,489.23 cw(c628.33,482.22) U1.36@633.29,487.18 ; 628.33,489.23 ccw(c628.33,496.25) U1.36@633.29,491.29 ; 628.33,489.23 ccw(c628.33,496.25) U1.36@633.29,491.29 ; 628.33,489.23 cw(c628.33,482.22) U1.36@633.29,487.18 ; 628.33,489.23 ccw(c628.33,496.25) U1.36@633.29,491.29 ; 628.33,489.23 cw(c628.33,482.22) U1.36@633.29,487.18
  Bottom Layer w6: X1.25 325,301.1 345.2,321.3 v1(345.2,396.4)
PB1: U1.30 X1.17 | length 776.5
  Top Layer w6: v1(174.4,908.3) 205.2,877.5 v1(417,877.5) ; v1@458.6,591.8 v1(461.9,588.5) 468.9,581.5 606.4,581.5 632.24,607.34 U1.30
  Bottom Layer w6: X1.17@174.9,863.6 X1.17 ; v1@416.5,877 416.5,772.3 404.2,760 404.2,692.8 411.4,685.6 411.4,685.14 442.9,653.64 442.9,607.5 v1(461.9,588.5)
PB2: U1.31 X1.18 | length 898.3
  Top Layer w6: v1(217.7,572.3) 249.5,540.5 382,540.5 412,570.5 616.4,570.5 633.56,587.66 U1.31
  Bottom Layer w6: X1.18 125.7,969.3 125.7,664.3 v1(217.7,572.3)
PB3: U1.19 X1.6 | length 264.9
  Top Layer w6: v1(715.7,925.6) 715.7,838.5 769.6,784.6 769.6,734.9 U1.19
  Bottom Layer w6: v1(715.7,925.6) 715.7,960.7 X1.6
PB4: U1.20 X1.8 | length 332.7
  Top Layer w6: v1(625.4,887.4) 641.1,887.4 752.47,776.03 U1.20 ; U1.20@750.42,746.21 ccw(c745.46,751.17) 752.47,751.17 ; U1.20@750.42,746.21 ccw(c745.46,751.17) 752.47,751.17 ; U1.20@750.42,746.21 ccw(c745.46,751.17) 752.47,751.17 ; 752.47,751.17 ccw(c759.49,751.17) U1.20@754.53,746.21 ; 752.47,751.17 ccw(c759.49,751.17) U1.20@754.53,746.21 ; 752.47,751.17 ccw(c759.49,751.17) U1.20@754.53,746.21
  Bottom Layer w6: X1.8 625.4,969.6 v1(625.4,887.4)
PB5: U1.43 X1.30 | length 419.8
  Top Layer w6: v1(575,286) 584.5,295.5 733.5,295.5 759.69,321.69 759.69,415.51 791.84,447.66 U1.43
  Bottom Layer w6: X1.30 v1(575,286)
PB6: U1.42 X1.29 | length 556.8
  Top Layer w5: v1(525,286) 545,306 725.1,306 749.19,330.09 749.19,419.86 772.16,442.83 U1.42
  Bottom Layer w5: X1.29 v1(525,286)
PB7: Q3.1 R36.1 U1.41 X1.28 | length 1071.1
  Top Layer w5: Q3.1 197.71,436.1 246.61,484.99 246.61,501.24 R36.1 256.37,513.17 384.17,513.17 v1(418,547) ; v1(474.6,315.8) 474.8,316 717.7,316 739.19,337.49 739.19,424 752.47,437.28 U1.41
  Bottom Layer w5: v1(418,547) 464.7,500.3 464.7,325.7 v1(474.6,315.8) 475,315.4 X1.28
PC0: J1.3 U1.40 X1.27 | length 1219.4
  Top Layer w6: J1.3 225,199.5 v1(241.5,216) ; v1(270.3,392.3) 287.3,375.3 314.74,375.3 316.94,377.5 366.1,377.5 v1(366.2,377.4) 380.6,363 539.6,363 576.1,326.5 708.6,326.5 728.69,346.59 728.69,428.35 732.79,432.45 U1.40
  Bottom Layer w6: v1(241.5,216) 241.5,283.9 269.8,312.2 269.8,391.8 v1(270.3,392.3) ; v1(366.2,377.4) 366.2,292.3 343.7,269.8 343.7,176.8 374.3,146.2 412.8,146.2 425,134 X1.27
PC1: U1.38 X1.26 | length 508.7
  Top Layer w6: v1(396.5,381.5) 535,381.5 567.5,414 658,414 693.42,449.42 U1.38
  Bottom Layer w6: X1.26 375,246 396.5,267.5 v1(396.5,381.5)
PC2: J1.2 U1.33 X1.22 | length 718.1
  Top Layer w6: v1(148,219.5) 148,231.5 164,247.5 164,283.5 J1.2 175,341.31 261.29,427.6 304.39,427.6 313.19,436.4 398.28,436.4 473.19,511.31 519.31,511.31 544.7,536.7 622.7,536.7 634.29,548.29 U1.33
  Bottom Layer w6: v1(148,219.5) 148.5,220 X1.22
PC3: J1.4 U1.34 X1.23 | length 762.4
  Top Layer w6: v1(207,216.5) 207,233 225,251 J1.4 225,375.76 264.04,414.8 307.14,414.8 317.74,425.4 402.83,425.4 477.74,500.31 530.51,500.31 549.7,519.5 626.21,519.5 635.31,528.6 U1.34
  Bottom Layer w6: v1(207,216.5) 225,198.5 X1.23
PC4: J1.7 U1.35 X1.24 | length 699.7
  Top Layer w6: v1(303.7,395.8) 322.3,414.4 407.39,414.4 482.3,489.31 540.91,489.31 554.3,502.7 627.3,502.7 633.52,508.92 U1.35 ; v1(306.5,214.5) 325,196 J1.7
  Bottom Layer w6: v1(303.7,395.8) 304,395.5 304,271.6 275,242.6 X1.24 280.5,214.5 v1(306.5,214.5)
PC5: U1.11 X1.2 | length 330.9
  Top Layer w6: U1.11 930.08,686.08 950,706 950,765.5 v1(949.5,766)
  Bottom Layer w6: X1.2 927.5,967.5 927.5,904 923,899.5 922.68,899.5 909.5,886.32 909.5,806 v1(949.5,766)
PC6: C10.1 U1.13 X1.3 Y2.1 | length 334.6
  Top Layer w6: v1(875,927.5) 875,940.22 Y2.1 904.4,962 922.3,944.1 C10.1 ; Y2.1@875,961.5 Y2.1@876.5,963 ; U1.13 890.27,744.27 898.5,752.5 v1@898.5,766.5
  Bottom Layer w6: v1(875,927.5) X1.3 875,823.5 887.5,811 887.5,777.5 v1@898.5,766.5
  other v1: 898.5,766
PC7: C9.1 U1.14 X1.4 Y2.2 | length 498.8
  Top Layer w6: Y2.2 Y2.2@808.5,962 ; v1@825.2,925.8 v1(825,925.6) 825,954 817,962 Y2.2@808.5,962 ; U1.14 870.58,765.58 v1@872.5,767.5 ; C9.1 952.08,1001.12 847.62,1001.12 Y2.2@808.5,962
  Bottom Layer w6: X1.4 v1(825,925.6) 850,900.6 850,826.44 876.5,799.94 876.5,770 v1(872.5,766)
RF_N: BLN1.3 L4.1 U1.4 | length 195.8
  Top Layer w7: U1.4 918.13,547 1037.5,547 1037.5,570.68 BLN1.3 1038.52,576.3 L4.1
RF_P: BLN1.4 L4.2 U1.3 | length 198.2
  Top Layer w7: U1.3@904.84,530.6 U1.3@906.79,528.66 ; U1.3 918.24,530 1037.5,530 1037.5,506.45 BLN1.4 1039.18,501.5 L4.2
TX_ALT_N: U1.7
TX_ALT_P: U1.6
VBRD: C3.1 C4.1 C5.1 C7.1 C37.1 J1.1 R10.2 R19.2 R24.2 U1.16 U1.23 U1.28 U1.37 U11.8 X1.32 | length 3307.8
  Top Layer w6: R19.2@61,775.5 R24.2
  Top Layer w8: R19.2@50.2,777.3 R19.2@56.5,771
  Top Layer w10: R24.2 101.13,784.63 124.4,807.9 270.5,807.9 293.43,784.97 R10.2 299.53,772 C37.1
  Top Layer w11: C4.1 530,636.5 540.21,646.71 U1.28 ; C5.1 530,742 551.9,763.9 682.02,763.9 693.42,752.5 U1.23 ; C3.1 539.56,439.94 547.81,431.69 653.19,431.69 673.73,452.23 U1.37 ; U1.16 831.21,756.72 833.13,758.64 833.13,777.9 833,778.03 833,807 C7.1 849.5,834.5 844.5,834.5 833.5,845.5 832,845.5 v1(832,843) ; 686.82,759.09 cw(c671.88,744.15) U1.23@693.01,744.15 ; 686.82,759.09 cw(c671.88,744.15) U1.23@693.01,744.15 ; 686.82,759.09 cw(c671.88,744.15) U1.23@693.01,744.15
  Top Layer w20: U11.8@336.06,724.1 C37.1 336.06,815.78 359.28,839 436.5,839 436.6,839.1 v1(491.5,784.2) ; v1(492.5,618.5) C4.1 ; v1(493.5,459.5) 494.5,458.5 C3.1 ; v1@494.5,724.5 C5.1
  Top Layer w25: U11.8@336.06,724.1 U11.8@337.66,722.5
  Top Layer w30: J1.1 175,167 152.5,189.5 135.57,189.5 114.5,210.57 114.5,356 143.79,385.29 184.29,385.29 272.57,473.57 274.78,473.57 282.21,481 394.79,481 459.1,545.31 v1(492,545.31)
  Bottom Layer w12: v1(491.5,784.2) 515.75,808.45 701.75,808.45 720.3,827 720.3,883.6 755.5,918.8 793.2,918.8 832,880 v1(832,843)
  Bottom Layer w30: v1(491.5,784.2) v1(491.5,721.5) 492.5,720.5 v1(492.5,618.5) v1(492,545.31) 492,417.5 659.35,250.15 ; X1.32 X1.32@675,234.5 ; 659.35,250.15 X1.32@675,234.5 ; 659.35,250.15 659.5,250.3 675,250.3 X1.32@675,234.5
pads on no net: AT1.2 BLN1.6 U1.9

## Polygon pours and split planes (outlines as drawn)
GND on Bottom Layer "Bottom Layer-No Net" (solid, pour order 3): 1620,10 1620,1006 10,1006 10,10

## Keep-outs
Keep-Out Layer:
  text ".Layer_Name" at 3975,-2617 h70

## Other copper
Top Layer:
  region net NetAT1_4: 1546,307 1564,307 1564,565.1 1541.1,588 1460.8,588 1460.8,560.2 1535.5,560.2 1535.6,317.4
  region net NetJ4_1: 1441.4,685.6 1441.4,600.6 1413.6,600.6 1413.6,685.6
  region net NetJ4_1: 1464.8,626.2 1464.8,600.6 1391.7,600.6 1391.7,626.2
  region net NetC19_1: 1313.6,588 1421.3,588 1421.3,560.2 1313.6,560.2
  region net NetC18_1: 1200.2,587.8 1303.8,587.8 1303.8,560.2 1200.2,560.2
  region net NetBLN1_1: 1190.3,587.8 1190.3,560.2 1085.2,560.2 1085.2,587.8
  region net GND: 1587.6,389.95 1587.6,256 1620.6,256 1620.6,389.95
  region net GND: 1374.1,256 1374.1,10.1 1253.6,10.1 1249.2,14.5 1249.2,28.5 1260.2,39.5 1344.7,39.5 1344.7,283.2 1478.3,283.1 1491.74,283.09 1511.1,263.87 1511.1,256
  text ".Layer_Name" at 3975,-2617 h70
Bottom Layer:
  text ".Layer_Name" at 3975,-2617 h70

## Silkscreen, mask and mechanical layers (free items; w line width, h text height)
Top Overlay:
  text ".Layer_Name" at 3975,-2617 h70
Bottom Overlay:
  text ".Layer_Name" at 3975,-2617 h70
Top Paste:
  text ".Layer_Name" at 3975,-2617 h70
Bottom Paste:
  text ".Layer_Name" at 3975,-2617 h70
Top Solder:
  text ".Layer_Name" at 3975,-2617 h70
Bottom Solder:
  text ".Layer_Name" at 3975,-2617 h70
Drill Guide:
  text ".Layer_Name" at 3975,-2617 h70
M1 Top Assembly:
  text ".Layer_Name" at 3975,-2617 h70
M2 Bottom Assembly:
  text ".Layer_Name" at 3975,-2617 h70
M7 Board Outline:
  the board outline again, w1
M13 Top 3D:
  text ".Layer_Name" at 3975,-2617 h70
M16 Sheet Border:
  lines w5: -2375,-1021 -2175,-1021 ; -2375,851 -2175,851 ; -2375,2731 -2175,2731 ; -2183.6,-1982.6 2654.4,-1982.6 ; -2175,-2181 2663,-2181 ; 1,-2897 1,-2697 ; 1,4403 1,4603 ; 1025,-2697 2663,-2697 2663,-1497 3925,-1497 ; 2373,-2897 2373,-2697 ; 2373,4403 2373,4603 ; 2425,-2697 6925,-2697 ; 3923,-2397 6925,-2397 ; 3923,-2097 6925,-2097 ; 3923,-1797 6928,-1797 ; 3925,-2697 3925,-2097 3925,-1497 ; 4750,-2897 4750,-2697 ; 4750,4403 4750,4603 ; 6025,-2697 6025,-2097 ; 6925,-1021 7125,-1021 ; 6925,851 7125,851 ; 6925,2731 7125,2731 ; 3925,-1497 6925,-1497 6925,-2697 ; 6925,-2697 -2175,-2697 -2175,4403 6925,4403 6925,-2697 ; -2375,-2897 -2375,4603 7125,4603 7125,-2897 -2375,-2897
  text "1" at -1202.66,4468 h70
  text "2" at 1155.35,4468 h70
  text "3" at 3532,4468 h70
  text "4" at 5907.35,4468 h70
  text "1" at -1202.66,4458.8 h70
  text "2" at 1155.35,4458.8 h70
  text "3" at 3532,4458.8 h70
  text "A" at -2300,3578 h70
  text "A" at 6995,3578 h70
  text "B" at -2300,1702 h70
  text "B" at 6995,1702 h70
  text "C" at -2300,-174 h70
  text "C" at 6995,-174 h70
  text "TITLE:" at 3975,-1597 h45
  text ".Title" at 3975,-1717 h70
  text "FILE NAME:" at 3975,-1897 h45
  text ".Pcb_File_Name_No_Path" at 3975,-2017 h70
  text "D" at -2300,-2046 h70
  text "D" at 6995,-2046 h70
  text ".Company Design Group" at -1315.4,-2121.8 h70
  text "Board NO.:" at 3975,-2197 h45
  text "REV:" at 6075,-2197 h45
  text ".Company Address 1" at 2720,-2217 h70
  text "The information in this document is subject to change without notice. The statements, configurations," at -2080,-2297 h45
  text ".Company Address 2" at 2720,-2317 h70
  text ".Board No" at 3975,-2317 h70
  text ".Board Rev" at 6075,-2317 h70
  text "technical data and recommendations in this  document are believed to be accurate and reliable, but are" at -2080,-2372 h45
  text ".Company Address 3" at 2720,-2417 h70
  text "presented without express or implied warranty. The information in this document is  the proprietary and" at -2080,-2447 h45
  text "Layer:" at 3975,-2497 h45
  text "DATE:" at 6075,-2497 h45
  text ".Company Web Site" at 2720,-2517 h70
  text "confidential property of Ember Corporation and is priviliged. No part of the drawing or information may" at -2080,-2522 h45
  text "be duplicated or otherwise  used without the express permission of Ember Corporation" at -2080,-2597 h45
  text ".Company Tel" at 2720,-2617 h70
  text ".Print_Date" at 6075,-2617 h70
  text "1" at -1202.66,-2832 h70
  text "2" at 1155.35,-2832 h70
  text "3" at 3532,-2832 h70
  text "4" at 5907.35,-2832 h70
Drill Drawing:
  drawing of 257 lines, arcs and shapes, not listed
  text "Fabrication Notes:" at -2077.4,4230.7 h70
  text "1. All dimensions in inches.  Tolerance = +/- 0.005\" unless noted otherwise" at -2077.4,4130.7 h45
  text "2. All materials: laminates, resins, metallizations and soldermask to be compliant to EU RoHS directive 2002/95/EC IAW SP-12509-01." at -2077.4,4055.7 h45
  text "3. 370 HR FR-4 or similar grade glass epoxy." at -2077.4,3980.7 h45
  text "4. Tg > 170 degrees celcius, glass transition temperature." at -2077.4,3905.7 h45
  text "5. TD > 350 degrees celcius, thermal decomposition." at -2077.4,3830.7 h45
  text "6. Er = 4.0 +/- 5% @ 2.5GHz." at -2077.4,3755.7 h45
  text "7. Minimum flammability rating UL94V-0, maximum dissipation factor 0.025." at -2077.4,3680.7 h45
  text "8. Adjust prepreg for 0.062\", +/- 0.003\" finished thickness measured over soldermask." at -2077.4,3605.7 h45
  text "9. Copper thickness 0.0014\", (1 oz)." at -2077.4,3530.7 h45
  text "10. Hole size tolerance = +/- 0.003\" unless noted otherwise." at -2077.4,3455.7 h45
  text "11. Hole centers and pad centers to be concentric within 0.002\"." at -2077.4,3380.7 h45
  text "12. Drill chart dimensions are drill sizes and not finished hole sizes." at -2077.4,3305.7 h45
  text "13. Finish - immersion gold over nickel.  No exposed bare copper permitted." at -2077.4,3230.7 h45
  text "14. Thieving not allowed on layer 1." at -2077.4,3155.7 h45
  text "15. Solder mask over bare copper, LPI class 2 gen. industrial registration +/- 0.004\"." at -2077.4,3080.7 h45
  text "16. No coverage on solder pads permitted." at -2077.4,3005.7 h45
  text "17. Refer to soldermask gerbers for tenting of vias." at -2077.4,2930.7 h45
  text "18. White silkscreen legend over red soldermask - both sides." at -2077.4,2855.7 h45
  text "19. Manufacturer icons not permitted on the silkscreen top layer." at -2077.4,2780.7 h45
  text "20. PCB serialization/panel placement ID on silkscreen bottom." at -2077.4,2705.7 h45
  text "21. Full electrical test against IPC-356A netlist." at -2077.4,2630.7 h45
  text "Layer" at 2023.4,1106.5 h60
  text "Name" at 2433.31,1106.5 h60
  text "Material" at 3363.06,1106.5 h60
  text "Thickness" at 4222.82,1106.5 h60
  text "Constant" at 4872.66,1106.5 h60
  text "Board Layer Stack" at 5442.52,1106.5 h60
  text "1" at 2023.4,986.5 h60
  text "Top Paste" at 2433.31,986.5 h60
  text "2" at 2023.4,866.5 h60
  text "Top Overlay" at 2433.31,866.5 h60
  text "3" at 2023.4,746.5 h60
  text "Top Solder" at 2433.31,746.5 h60
  text "Solder Resist" at 3363.06,746.5 h60
  text "0.40mil" at 4222.82,746.5 h60
  text "3.5" at 4872.66,746.5 h60
  text "4" at 2023.4,626.5 h60
  text "Top Layer" at 2433.31,626.5 h60
  text "Copper" at 3363.06,626.5 h60
  text "1.40mil" at 4222.82,626.5 h60
  text "5" at 2023.4,506.5 h60
  text "Dielectric1" at 2433.31,506.5 h60
  text "HR370" at 3363.06,506.5 h60
  text "58.00mil" at 4222.82,506.5 h60
  text "3.9" at 4872.66,506.5 h60
  text "6" at 2023.4,386.5 h60
  text "Bottom Layer" at 2433.31,386.5 h60
  text "Copper" at 3363.06,386.5 h60
  text "1.40mil" at 4222.82,386.5 h60
  text "7" at 2023.4,266.5 h60
  text "Bottom Solder" at 2433.31,266.5 h60
  text "Solder Resist" at 3363.06,266.5 h60
  text "0.40mil" at 4222.82,266.5 h60
  text "3.5" at 4872.66,266.5 h60
  text "8" at 2023.4,146.5 h60
  text "Bottom Overlay" at 2433.31,146.5 h60
  text "9" at 2023.4,26.5 h60
  text "Bottom Paste" at 2433.31,26.5 h60
  text "Symbol" at 2062.6,-282.7 h72
  text "Hit Count" at 2568.48,-282.7 h72
  text "Finished Hole Size" at 3266.29,-282.7 h72
  text "Plated" at 4611.89,-282.7 h72
  text "Hole Type" at 5117.77,-282.7 h72
  text "127" at 2568.48,-432.7 h60
  text "10.00mil (0.254mm)" at 3266.29,-432.7 h60
  text "PTH" at 4611.89,-432.7 h60
  text "Round" at 5117.77,-432.7 h60
  text "127 Total" at 2568.48,-582.7 h60
  text ".Layer_Name" at 3975,-2617 h70

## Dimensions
0,1016 to 1630,1016 on Drill Drawing
0,1016 to 0,0 on Drill Drawing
